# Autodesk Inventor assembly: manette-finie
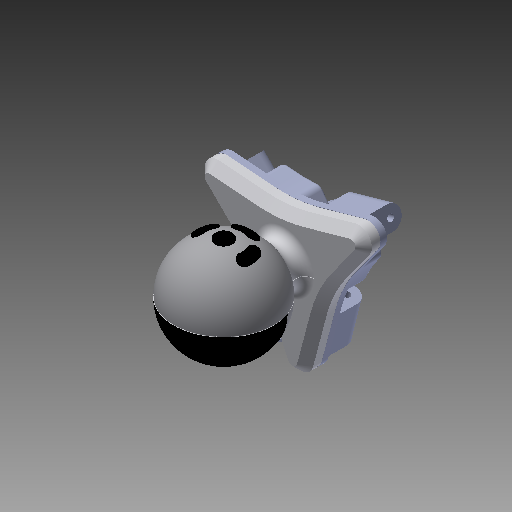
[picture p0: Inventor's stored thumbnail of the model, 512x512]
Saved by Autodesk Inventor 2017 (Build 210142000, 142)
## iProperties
Created: 2013-10
Part Number: manette-finie
Material: Générique
Document SubType Name: Assembly
Designer: Bruno
Mass: 103.089 g
Surface Area: 280.465 cm^2
Volume: 101.068 cm^3
Density: 1.02 g/cm^3
Sending System: SolidWorks 2013
Last Author: christophe
Last Saved: 2014-02-15
Author: Bruno
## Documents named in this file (4)
- D:\Cours\1-Cours-2018-19\1Ssi\7- EDC-mvt\Haptique-2017\Reel-Inventor\manette-finie.iam
- D:\Cours\1-Cours-2018-19\1Ssi\7- EDC-mvt\Haptique-2017\Reel-Inventor\manette.iam
- D:\Cours\1-Cours-2018-19\1Ssi\7- EDC-mvt\Haptique-2017\Reel-Inventor\manette2.ipt
- D:\Cours\1-Cours-2018-19\1Ssi\7- EDC-mvt\Haptique-2017\Reel-Inventor\BASE.ipt
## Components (3 placed, 3 different names)
1. manette:1 [sub-assembly] — Affleurement:1, Placage:1, Placage:2
2. manette2:1
3. BASE:1 — Affleurement:1, Placage:1, Placage:2
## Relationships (3: Mate 2, Flush 1)
- Affleurement:1 [Flush]: manette:1 ↔ BASE:1
- Placage:1 [Mate]: manette:1 ↔ BASE:1
- Placage:2 [Mate]: manette:1 ↔ BASE:1
